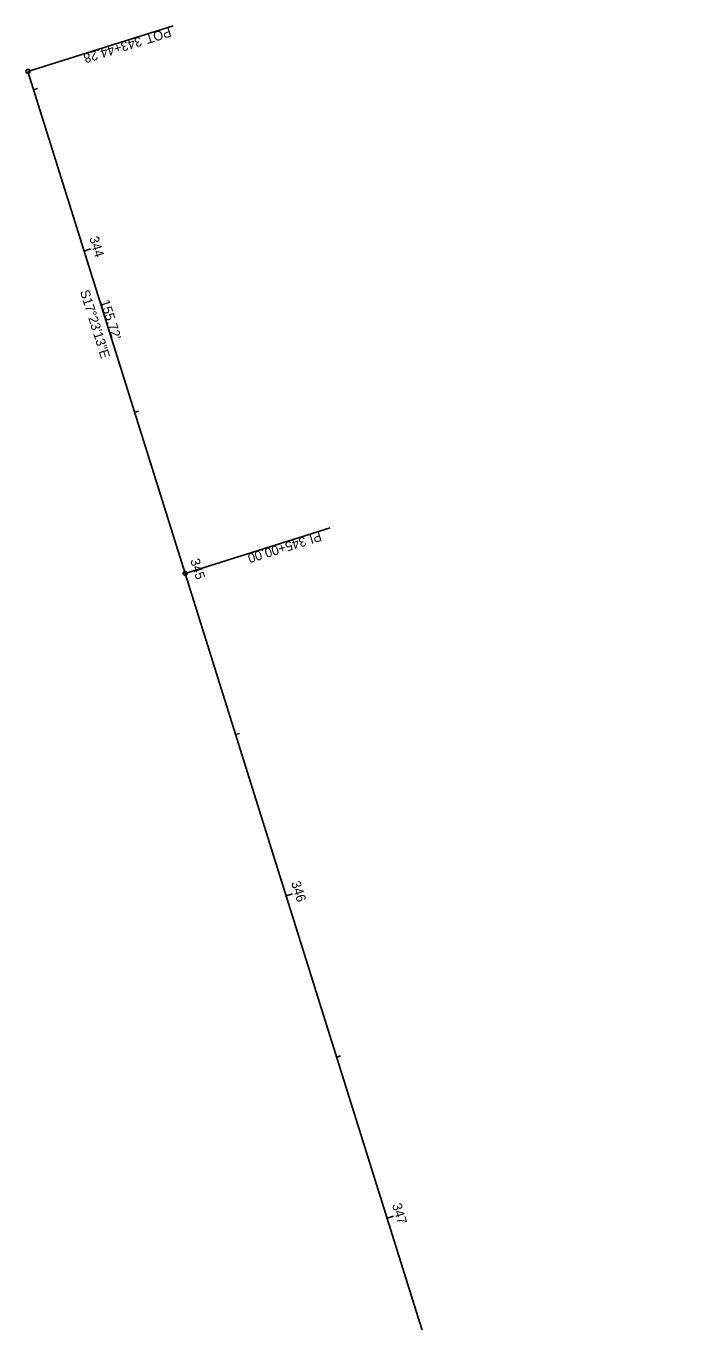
# Model space of a CAD drawing. Extents: x 1918148 to 1920349, y 624677 to 627727.
# Drawn here: x 1918670.8 to 1918867.4, y 627343.9 to 627727.3 of the extents above; entities that cross this region are included whole.
import ezdxf

# ---------------------------------------------------------------- set-up
doc = ezdxf.new("R2010")
doc.units = 0
for name, color, linetype in [('_CIVIL_CONSTRUCTION', 7, 'Continuous'), ('RS_Raster1', 7, 'Continuous'), ('RW_X_CL', 7, 'Continuous'), ('RW_X_CL_100_Cardinal_Points', 7, 'Continuous'), ('RW_X_CL_100_Curve_Data', 7, 'Continuous')]:
    doc.layers.add(name, color=color, linetype=linetype)

msp = doc.modelspace()

# ---------------------------------------------------------------- linework, layer by layer
at = {"layer": 'RS_Raster1'}
for p, q in [((1918671.41, 627713.83), (1918717.94, 627565.23)), ((1918717.94, 627565.23), (1918867.35, 627088.08))]:
    msp.add_line(p, q, dxfattribs=at)
at = {"layer": 'RW_X_CL'}
for p, q in [((1918671.41, 627713.83), (1918714.35, 627727.28)), ((1918717.94, 627565.23), (1918760.89, 627578.68))]:
    msp.add_line(p, q, dxfattribs=at)
for centre in [(1918671.41, 627713.83), (1918717.94, 627565.23)]:
    msp.add_circle(centre, 0.6, dxfattribs=at)
at = {"layer": 'RW_X_CL_100_Cardinal_Points'}
for p, q in [((1918673.12, 627708.38), (1918674.26, 627708.73)), ((1918688.06, 627660.66), (1918689.97, 627661.26)), ((1918703, 627612.95), (1918704.15, 627613.3)), ((1918717.94, 627565.23), (1918719.85, 627565.83)), ((1918732.88, 627517.51), (1918734.03, 627517.87)), ((1918747.82, 627469.8), (1918749.73, 627470.4)), ((1918762.77, 627422.08), (1918763.91, 627422.44)), ((1918777.71, 627374.37), (1918779.62, 627374.97))]:
    msp.add_line(p, q, dxfattribs=at)

# ---------------------------------------------------------------- texts
at = {"layer": '_CIVIL_CONSTRUCTION'}
msp.add_text('S17°23\'13"E', height=2.8, rotation=287.387, dxfattribs=at).set_placement((1918686.79, 627648.67))
at = {"layer": 'RW_X_CL'}
for s, p in [('343+44.28', (1918704.58, 627724.17)), ('POT', (1918713.3, 627726.9)), ('345+00.00', (1918753.19, 627576.22)), ('PI', (1918757.76, 627577.65))]:
    msp.add_text(s, height=2.8, rotation=197.387, dxfattribs=at).set_placement(p)
at = {"layer": 'RW_X_CL_100_Cardinal_Points'}
for s, p in [('344', (1918689.52, 627664.51)), ('345', (1918719.39, 627569.13)), ('346', (1918749.27, 627473.69)), ('347', (1918779.14, 627378.32))]:
    msp.add_text(s, height=2.8, rotation=287.387, dxfattribs=at).set_placement(p)
at = {"layer": 'RW_X_CL_100_Curve_Data'}
msp.add_text("155.72'", height=2.8, rotation=287.387, dxfattribs=at).set_placement((1918692.78, 627645.74))

doc.saveas('drawing.dxf')
